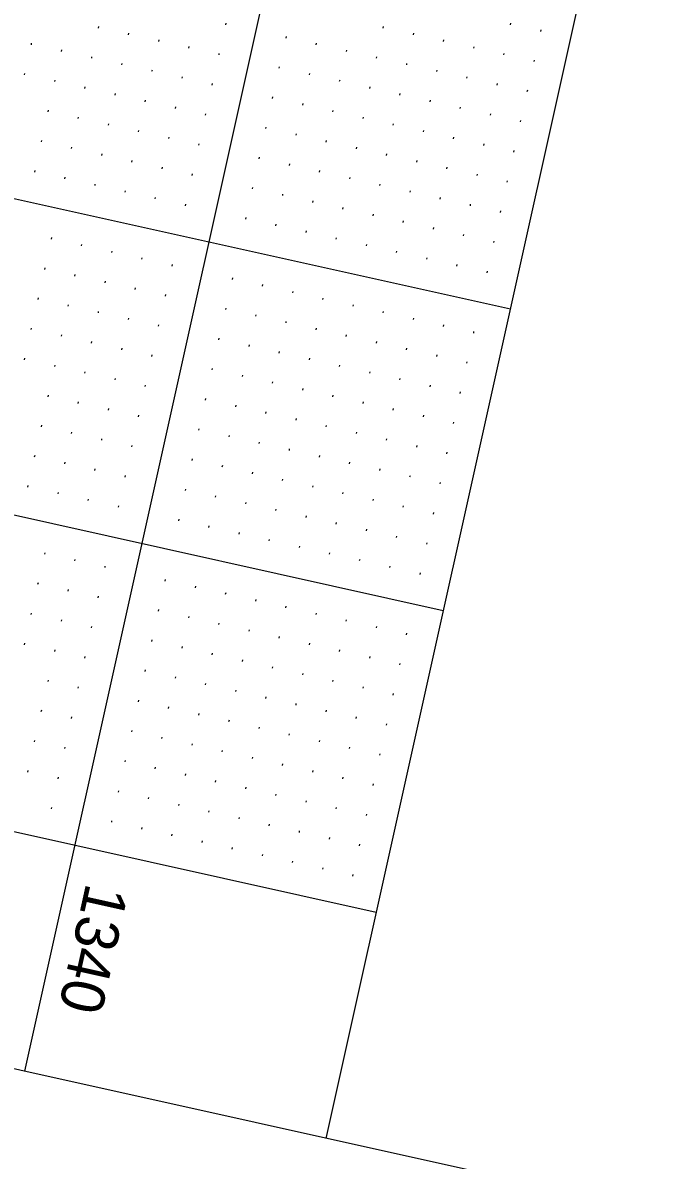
# Model space of a CAD drawing. Extents: x 2149268 to 2150830, y 142155 to 144285.
# Drawn here: x 2149815.9 to 2149919.9, y 142325.7 to 142509.8 of the extents above; entities that cross this region are included whole.
import ezdxf

# ---------------------------------------------------------------- set-up
doc = ezdxf.new("R2010")
doc.units = 0
for name, color, linetype in [('SHT_Plan_Profile_Sheet_Elev_Txt', 7, 'Continuous'), ('SHT_Profile_Grid_Major', 7, 'Continuous'), ('SHT_Profile_Grid_Minor', 7, 'Continuous'), ('SHT_Sheet_Border', 7, 'Continuous')]:
    doc.layers.add(name, color=color, linetype=linetype)

msp = doc.modelspace()

# ---------------------------------------------------------------- linework, layer by layer
at = {"layer": 'SHT_Profile_Grid_Major'}
for p, q in [((2150158.06, 143877.55), (2149816.2, 142340.1)), ((2149504.39, 142550.29), (2149894.85, 142463.47)), ((2149493.54, 142501.48), (2149884, 142414.66))]:
    msp.add_line(p, q, dxfattribs=at)
at = {"layer": 'SHT_Profile_Grid_Minor'}
for p, q in [((2149828.18, 142509.15), (2149828.12, 142508.91)), ((2149833.06, 142508.07), (2149833.01, 142507.82)), ((2149848.79, 142509.69), (2149848.73, 142509.45)), ((2149874.28, 142509.15), (2149874.22, 142508.9)), ((2149879.16, 142508.06), (2149879.1, 142507.82)), ((2149894.88, 142509.69), (2149894.83, 142509.44)), ((2149899.77, 142508.6), (2149899.71, 142508.36)), ((2149817.33, 142506.44), (2149817.28, 142506.2)), ((2149837.94, 142506.98), (2149837.89, 142506.74)), ((2149858.55, 142507.52), (2149858.49, 142507.28)), ((2149863.43, 142506.44), (2149863.38, 142506.19)), ((2149884.04, 142506.98), (2149883.98, 142506.73)), ((2149822.21, 142505.36), (2149822.16, 142505.11)), ((2149827.09, 142504.27), (2149827.04, 142504.03)), ((2149842.82, 142505.9), (2149842.77, 142505.65)), ((2149847.7, 142504.81), (2149847.65, 142504.57)), ((2149868.31, 142505.35), (2149868.26, 142505.11)), ((2149873.19, 142504.27), (2149873.14, 142504.02)), ((2149888.92, 142505.89), (2149888.86, 142505.65)), ((2149893.8, 142504.81), (2149893.75, 142504.56)), ((2149831.97, 142503.19), (2149831.92, 142502.94)), ((2149857.46, 142502.64), (2149857.41, 142502.4)), ((2149878.07, 142503.18), (2149878.02, 142502.94)), ((2149898.68, 142503.72), (2149898.63, 142503.48)), ((2149816.25, 142501.56), (2149816.19, 142501.32)), ((2149836.86, 142502.1), (2149836.8, 142501.86)), ((2149841.74, 142501.02), (2149841.68, 142500.77)), ((2149862.34, 142501.56), (2149862.29, 142501.31)), ((2149882.95, 142502.1), (2149882.9, 142501.85)), ((2149887.83, 142501.01), (2149887.78, 142500.77)), ((2149821.13, 142500.48), (2149821.07, 142500.23)), ((2149826.01, 142499.39), (2149825.95, 142499.15)), ((2149846.62, 142499.93), (2149846.56, 142499.69)), ((2149867.23, 142500.47), (2149867.17, 142500.23)), ((2149872.11, 142499.39), (2149872.05, 142499.14)), ((2149892.71, 142499.92), (2149892.66, 142499.68)), ((2149897.6, 142498.84), (2149897.54, 142498.6)), ((2149830.89, 142498.31), (2149830.83, 142498.06)), ((2149835.77, 142497.22), (2149835.72, 142496.98)), ((2149856.38, 142497.76), (2149856.32, 142497.52)), ((2149876.99, 142498.3), (2149876.93, 142498.06)), ((2149881.87, 142497.21), (2149881.81, 142496.97)), ((2149820.04, 142495.6), (2149819.99, 142495.35)), ((2149840.65, 142496.14), (2149840.6, 142495.89)), ((2149845.53, 142495.05), (2149845.48, 142494.81)), ((2149861.26, 142496.67), (2149861.2, 142496.43)), ((2149866.14, 142495.59), (2149866.09, 142495.35)), ((2149886.75, 142496.13), (2149886.69, 142495.89)), ((2149891.63, 142495.04), (2149891.57, 142494.8)), ((2149824.92, 142494.51), (2149824.87, 142494.27)), ((2149829.8, 142493.43), (2149829.75, 142493.18)), ((2149871.02, 142494.5), (2149870.97, 142494.26)), ((2149875.9, 142493.42), (2149875.85, 142493.18)), ((2149896.51, 142493.96), (2149896.46, 142493.71)), ((2149834.68, 142492.34), (2149834.63, 142492.1)), ((2149855.29, 142492.88), (2149855.24, 142492.64)), ((2149860.17, 142491.79), (2149860.12, 142491.55)), ((2149880.78, 142492.33), (2149880.73, 142492.09)), ((2149818.96, 142490.71), (2149818.9, 142490.47)), ((2149823.84, 142489.63), (2149823.78, 142489.39)), ((2149839.57, 142491.25), (2149839.51, 142491.01)), ((2149844.45, 142490.17), (2149844.39, 142489.93)), ((2149865.05, 142490.71), (2149865, 142490.46)), ((2149869.94, 142489.62), (2149869.88, 142489.38)), ((2149885.66, 142491.25), (2149885.61, 142491)), ((2149890.54, 142490.16), (2149890.49, 142489.92)), ((2149828.72, 142488.54), (2149828.66, 142488.3)), ((2149854.21, 142488), (2149854.15, 142487.75)), ((2149874.82, 142488.54), (2149874.76, 142488.29)), ((2149895.42, 142489.08), (2149895.37, 142488.83)), ((2149833.6, 142487.46), (2149833.55, 142487.22)), ((2149838.48, 142486.37), (2149838.43, 142486.13)), ((2149859.09, 142486.91), (2149859.03, 142486.67)), ((2149879.7, 142487.45), (2149879.64, 142487.21)), ((2149884.58, 142486.37), (2149884.52, 142486.12)), ((2149817.87, 142485.83), (2149817.82, 142485.59)), ((2149822.75, 142484.75), (2149822.7, 142484.5)), ((2149843.36, 142485.29), (2149843.31, 142485.04)), ((2149863.97, 142485.83), (2149863.92, 142485.58)), ((2149868.85, 142484.74), (2149868.8, 142484.5)), ((2149889.46, 142485.28), (2149889.4, 142485.04)), ((2149894.34, 142484.2), (2149894.29, 142483.95)), ((2149827.63, 142483.66), (2149827.58, 142483.42)), ((2149832.51, 142482.58), (2149832.46, 142482.33)), ((2149853.12, 142483.12), (2149853.07, 142482.87)), ((2149873.73, 142483.66), (2149873.68, 142483.41)), ((2149878.61, 142482.57), (2149878.56, 142482.33)), ((2149837.39, 142481.49), (2149837.34, 142481.25)), ((2149842.28, 142480.41), (2149842.22, 142480.16)), ((2149858, 142482.03), (2149857.95, 142481.79)), ((2149862.88, 142480.95), (2149862.83, 142480.7)), ((2149883.49, 142481.49), (2149883.44, 142481.24)), ((2149888.37, 142480.4), (2149888.32, 142480.16)), ((2149867.76, 142479.86), (2149867.71, 142479.62)), ((2149872.65, 142478.78), (2149872.59, 142478.53)), ((2149893.25, 142479.32), (2149893.2, 142479.07)), ((2149852.04, 142478.24), (2149851.98, 142477.99)), ((2149856.92, 142477.15), (2149856.86, 142476.91)), ((2149877.53, 142477.69), (2149877.47, 142477.45)), ((2149820.58, 142474.99), (2149820.53, 142474.74)), ((2149861.8, 142476.07), (2149861.74, 142475.82)), ((2149866.68, 142474.98), (2149866.63, 142474.74)), ((2149882.41, 142476.61), (2149882.35, 142476.36)), ((2149887.29, 142475.52), (2149887.23, 142475.28)), ((2149825.46, 142473.9), (2149825.41, 142473.66)), ((2149871.56, 142473.9), (2149871.51, 142473.65)), ((2149892.17, 142474.44), (2149892.11, 142474.19)), ((2149830.34, 142472.82), (2149830.29, 142472.57)), ((2149835.22, 142471.73), (2149835.17, 142471.49)), ((2149876.44, 142472.81), (2149876.39, 142472.57)), ((2149881.32, 142471.73), (2149881.27, 142471.48)), ((2149819.5, 142470.11), (2149819.44, 142469.86)), ((2149840.1, 142470.65), (2149840.05, 142470.4)), ((2149886.2, 142470.64), (2149886.15, 142470.4)), ((2149891.08, 142469.55), (2149891.03, 142469.31)), ((2149824.38, 142469.02), (2149824.32, 142468.78)), ((2149829.26, 142467.94), (2149829.2, 142467.69)), ((2149849.87, 142468.48), (2149849.81, 142468.23)), ((2149834.14, 142466.85), (2149834.08, 142466.61)), ((2149839.02, 142465.77), (2149838.97, 142465.52)), ((2149854.75, 142467.39), (2149854.69, 142467.15)), ((2149859.63, 142466.3), (2149859.57, 142466.06)), ((2149818.41, 142465.23), (2149818.36, 142464.98)), ((2149823.29, 142464.14), (2149823.24, 142463.9)), ((2149864.51, 142465.22), (2149864.45, 142464.98)), ((2149869.39, 142464.13), (2149869.34, 142463.89)), ((2149828.17, 142463.06), (2149828.12, 142462.81)), ((2149833.05, 142461.97), (2149833, 142461.73)), ((2149848.78, 142463.59), (2149848.73, 142463.35)), ((2149853.66, 142462.51), (2149853.61, 142462.27)), ((2149874.27, 142463.05), (2149874.22, 142462.81)), ((2149879.15, 142461.96), (2149879.1, 142461.72)), ((2149817.33, 142460.34), (2149817.27, 142460.1)), ((2149837.93, 142460.88), (2149837.88, 142460.64)), ((2149858.54, 142461.42), (2149858.49, 142461.18)), ((2149863.42, 142460.34), (2149863.37, 142460.09)), ((2149884.03, 142460.88), (2149883.98, 142460.63)), ((2149822.21, 142459.26), (2149822.15, 142459.02)), ((2149847.7, 142458.71), (2149847.64, 142458.47)), ((2149868.3, 142459.25), (2149868.25, 142459.01)), ((2149888.91, 142459.79), (2149888.86, 142459.55)), ((2149827.09, 142458.17), (2149827.03, 142457.93)), ((2149831.97, 142457.09), (2149831.91, 142456.84)), ((2149852.58, 142457.63), (2149852.52, 142457.38)), ((2149857.46, 142456.54), (2149857.4, 142456.3)), ((2149873.19, 142458.17), (2149873.13, 142457.92)), ((2149878.07, 142457.08), (2149878.01, 142456.84)), ((2149816.24, 142455.46), (2149816.19, 142455.22)), ((2149836.85, 142456), (2149836.79, 142455.76)), ((2149862.34, 142455.46), (2149862.28, 142455.21)), ((2149882.95, 142456), (2149882.89, 142455.75)), ((2149887.83, 142454.91), (2149887.77, 142454.67)), ((2149821.12, 142454.38), (2149821.07, 142454.13)), ((2149826, 142453.29), (2149825.95, 142453.05)), ((2149846.61, 142453.83), (2149846.56, 142453.59)), ((2149851.49, 142452.75), (2149851.44, 142452.5)), ((2149867.22, 142454.37), (2149867.16, 142454.13)), ((2149872.1, 142453.29), (2149872.05, 142453.04)), ((2149830.88, 142452.21), (2149830.83, 142451.96)), ((2149835.76, 142451.12), (2149835.71, 142450.88)), ((2149856.37, 142451.66), (2149856.32, 142451.42)), ((2149876.98, 142452.2), (2149876.93, 142451.96)), ((2149881.86, 142451.12), (2149881.81, 142450.87)), ((2149820.04, 142449.5), (2149819.98, 142449.25)), ((2149861.25, 142450.58), (2149861.2, 142450.33)), ((2149866.13, 142449.49), (2149866.08, 142449.25)), ((2149886.74, 142450.03), (2149886.69, 142449.79)), ((2149824.92, 142448.41), (2149824.86, 142448.17)), ((2149829.8, 142447.33), (2149829.74, 142447.08)), ((2149845.53, 142448.95), (2149845.47, 142448.71)), ((2149850.41, 142447.87), (2149850.35, 142447.62)), ((2149871.01, 142448.41), (2149870.96, 142448.16)), ((2149875.9, 142447.32), (2149875.84, 142447.08)), ((2149834.68, 142446.24), (2149834.62, 142446)), ((2149855.29, 142446.78), (2149855.23, 142446.54)), ((2149860.17, 142445.7), (2149860.11, 142445.45)), ((2149880.78, 142446.24), (2149880.72, 142445.99)), ((2149818.95, 142444.62), (2149818.9, 142444.37)), ((2149823.83, 142443.53), (2149823.78, 142443.29)), ((2149844.44, 142444.07), (2149844.39, 142443.83)), ((2149865.05, 142444.61), (2149864.99, 142444.37)), ((2149869.93, 142443.53), (2149869.88, 142443.28)), ((2149885.66, 142445.15), (2149885.6, 142444.91)), ((2149828.71, 142442.45), (2149828.66, 142442.2)), ((2149849.32, 142442.99), (2149849.27, 142442.74)), ((2149854.2, 142441.9), (2149854.15, 142441.66)), ((2149874.81, 142442.44), (2149874.76, 142442.2)), ((2149833.59, 142441.36), (2149833.54, 142441.12)), ((2149859.08, 142440.82), (2149859.03, 142440.57)), ((2149879.69, 142441.36), (2149879.64, 142441.11)), ((2149884.57, 142440.27), (2149884.52, 142440.03)), ((2149817.87, 142439.74), (2149817.81, 142439.49)), ((2149822.75, 142438.65), (2149822.69, 142438.41)), ((2149843.35, 142439.19), (2149843.3, 142438.95)), ((2149848.24, 142438.11), (2149848.18, 142437.86)), ((2149863.96, 142439.73), (2149863.91, 142439.49)), ((2149868.84, 142438.65), (2149868.79, 142438.4)), ((2149827.63, 142437.57), (2149827.57, 142437.32)), ((2149832.51, 142436.48), (2149832.45, 142436.24)), ((2149853.12, 142437.02), (2149853.06, 142436.78)), ((2149873.72, 142437.56), (2149873.67, 142437.32)), ((2149878.61, 142436.47), (2149878.55, 142436.23)), ((2149816.78, 142434.86), (2149816.73, 142434.61)), ((2149842.27, 142434.31), (2149842.22, 142434.07)), ((2149858, 142435.93), (2149857.94, 142435.69)), ((2149862.88, 142434.85), (2149862.82, 142434.61)), ((2149883.49, 142435.39), (2149883.43, 142435.15)), ((2149821.66, 142433.77), (2149821.61, 142433.53)), ((2149826.54, 142432.69), (2149826.49, 142432.44)), ((2149847.15, 142433.22), (2149847.1, 142432.98)), ((2149867.76, 142433.76), (2149867.7, 142433.52)), ((2149872.64, 142432.68), (2149872.59, 142432.44)), ((2149831.42, 142431.6), (2149831.37, 142431.36)), ((2149852.03, 142432.14), (2149851.98, 142431.9)), ((2149856.91, 142431.05), (2149856.86, 142430.81)), ((2149877.52, 142431.59), (2149877.47, 142431.35)), ((2149841.18, 142429.43), (2149841.13, 142429.19)), ((2149861.79, 142429.97), (2149861.74, 142429.72)), ((2149866.67, 142428.88), (2149866.62, 142428.64)), ((2149882.4, 142430.51), (2149882.35, 142430.26)), ((2149846.07, 142428.34), (2149846.01, 142428.1)), ((2149850.95, 142427.26), (2149850.89, 142427.01)), ((2149871.55, 142427.8), (2149871.5, 142427.55)), ((2149855.83, 142426.17), (2149855.77, 142425.93)), ((2149876.44, 142426.71), (2149876.38, 142426.47)), ((2149881.32, 142425.63), (2149881.26, 142425.38)), ((2149819.49, 142424.01), (2149819.44, 142423.76)), ((2149860.71, 142425.09), (2149860.65, 142424.84)), ((2149865.59, 142424), (2149865.53, 142423.76)), ((2149824.37, 142422.92), (2149824.32, 142422.68)), ((2149829.25, 142421.84), (2149829.2, 142421.59)), ((2149870.47, 142422.92), (2149870.41, 142422.67)), ((2149875.35, 142421.83), (2149875.3, 142421.59)), ((2149839.01, 142419.67), (2149838.96, 142419.42)), ((2149880.23, 142420.75), (2149880.18, 142420.5)), ((2149818.41, 142419.13), (2149818.35, 142418.88)), ((2149823.29, 142418.04), (2149823.23, 142417.8)), ((2149843.89, 142418.58), (2149843.84, 142418.34)), ((2149828.17, 142416.96), (2149828.11, 142416.71)), ((2149848.78, 142417.5), (2149848.72, 142417.25)), ((2149853.66, 142416.41), (2149853.6, 142416.17)), ((2149817.32, 142414.25), (2149817.27, 142414)), ((2149837.93, 142414.79), (2149837.87, 142414.54)), ((2149858.54, 142415.33), (2149858.48, 142415.08)), ((2149863.42, 142414.24), (2149863.36, 142414)), ((2149822.2, 142413.16), (2149822.15, 142412.92)), ((2149842.81, 142413.7), (2149842.76, 142413.46)), ((2149847.69, 142412.62), (2149847.64, 142412.37)), ((2149868.3, 142413.16), (2149868.24, 142412.91)), ((2149827.08, 142412.08), (2149827.03, 142411.83)), ((2149852.57, 142411.53), (2149852.52, 142411.29)), ((2149857.45, 142410.45), (2149857.4, 142410.2)), ((2149873.18, 142412.07), (2149873.13, 142411.83)), ((2149878.06, 142410.99), (2149878.01, 142410.74)), ((2149816.23, 142409.37), (2149816.18, 142409.12)), ((2149836.84, 142409.91), (2149836.79, 142409.66)), ((2149841.72, 142408.82), (2149841.67, 142408.58)), ((2149862.33, 142409.36), (2149862.28, 142409.12)), ((2149821.12, 142408.28), (2149821.06, 142408.04)), ((2149826, 142407.2), (2149825.94, 142406.95)), ((2149846.6, 142407.74), (2149846.55, 142407.49)), ((2149867.21, 142408.28), (2149867.16, 142408.03)), ((2149872.09, 142407.19), (2149872.04, 142406.95)), ((2149835.76, 142405.03), (2149835.7, 142404.78)), ((2149851.49, 142406.65), (2149851.43, 142406.41)), ((2149856.37, 142405.56), (2149856.31, 142405.32)), ((2149876.97, 142406.1), (2149876.92, 142405.86)), ((2149820.03, 142403.4), (2149819.98, 142403.16)), ((2149840.64, 142403.94), (2149840.58, 142403.7)), ((2149861.25, 142404.48), (2149861.19, 142404.24)), ((2149866.13, 142403.39), (2149866.07, 142403.15)), ((2149824.91, 142402.31), (2149824.86, 142402.07)), ((2149845.52, 142402.85), (2149845.47, 142402.61)), ((2149850.4, 142401.77), (2149850.35, 142401.53)), ((2149871.01, 142402.31), (2149870.95, 142402.06)), ((2149875.89, 142401.22), (2149875.84, 142400.98)), ((2149834.67, 142400.14), (2149834.62, 142399.9)), ((2149855.28, 142400.68), (2149855.23, 142400.44)), ((2149860.16, 142399.6), (2149860.11, 142399.35)), ((2149818.95, 142398.52), (2149818.89, 142398.28)), ((2149839.55, 142399.06), (2149839.5, 142398.82)), ((2149844.43, 142397.97), (2149844.38, 142397.73)), ((2149865.04, 142398.51), (2149864.99, 142398.27)), ((2149823.83, 142397.43), (2149823.77, 142397.19)), ((2149849.32, 142396.89), (2149849.26, 142396.64)), ((2149854.2, 142395.8), (2149854.14, 142395.56)), ((2149869.92, 142397.43), (2149869.87, 142397.18)), ((2149874.8, 142396.34), (2149874.75, 142396.1)), ((2149833.59, 142395.26), (2149833.53, 142395.02)), ((2149838.47, 142394.18), (2149838.41, 142393.93)), ((2149859.08, 142394.72), (2149859.02, 142394.47)), ((2149817.86, 142393.64), (2149817.81, 142393.39)), ((2149822.74, 142392.55), (2149822.69, 142392.31)), ((2149843.35, 142393.09), (2149843.29, 142392.85)), ((2149848.23, 142392.01), (2149848.18, 142391.76)), ((2149863.96, 142393.63), (2149863.9, 142393.39)), ((2149868.84, 142392.55), (2149868.78, 142392.3)), ((2149832.5, 142390.38), (2149832.45, 142390.14)), ((2149853.11, 142390.92), (2149853.06, 142390.68)), ((2149873.72, 142391.46), (2149873.66, 142391.22)), ((2149816.77, 142388.76), (2149816.72, 142388.51)), ((2149837.38, 142389.3), (2149837.33, 142389.05)), ((2149857.99, 142389.84), (2149857.94, 142389.59)), ((2149862.87, 142388.75), (2149862.82, 142388.51)), ((2149821.66, 142387.67), (2149821.6, 142387.43)), ((2149842.26, 142388.21), (2149842.21, 142387.97)), ((2149847.14, 142387.13), (2149847.09, 142386.88)), ((2149867.75, 142387.67), (2149867.7, 142387.42)), ((2149872.63, 142386.58), (2149872.58, 142386.34)), ((2149831.42, 142385.5), (2149831.36, 142385.26)), ((2149852.03, 142386.04), (2149851.97, 142385.8)), ((2149856.91, 142384.96), (2149856.85, 142384.71)), ((2149820.57, 142382.79), (2149820.52, 142382.55)), ((2149836.3, 142384.42), (2149836.24, 142384.17)), ((2149841.18, 142383.33), (2149841.12, 142383.09)), ((2149861.79, 142383.87), (2149861.73, 142383.63)), ((2149866.67, 142382.79), (2149866.61, 142382.54)), ((2149846.06, 142382.25), (2149846.01, 142382)), ((2149850.94, 142381.16), (2149850.89, 142380.92)), ((2149871.55, 142381.7), (2149871.49, 142381.46)), ((2149830.33, 142380.62), (2149830.28, 142380.38)), ((2149835.21, 142379.54), (2149835.16, 142379.29)), ((2149855.82, 142380.08), (2149855.77, 142379.83)), ((2149840.09, 142378.45), (2149840.04, 142378.21)), ((2149844.97, 142377.37), (2149844.92, 142377.12)), ((2149860.7, 142378.99), (2149860.65, 142378.75)), ((2149865.58, 142377.91), (2149865.53, 142377.66)), ((2149849.85, 142376.28), (2149849.8, 142376.04)), ((2149870.46, 142376.82), (2149870.41, 142376.58)), ((2149854.74, 142375.19), (2149854.68, 142374.95)), ((2149859.62, 142374.11), (2149859.56, 142373.87)), ((2149864.5, 142373.02), (2149864.44, 142372.78)), ((2149869.38, 142371.94), (2149869.32, 142371.69))]:
    msp.add_line(p, q, dxfattribs=at)
at = {"layer": 'SHT_Sheet_Border'}
for p, q in [((2150206.87, 143866.7), (2149865.01, 142329.24)), ((2149409.47, 142468.95), (2149873.15, 142365.85))]:
    msp.add_line(p, q, dxfattribs=at)
msp.add_lwpolyline([(2150726.67, 143751.11), (2150384.81, 142213.66), (2149359.84, 142441.57), (2149701.71, 143979.02)], close=True, dxfattribs=at)

# ---------------------------------------------------------------- texts
at = {"layer": 'SHT_Plan_Profile_Sheet_Elev_Txt'}
msp.add_text('1340', height=7, rotation=257.4638, dxfattribs=at).set_placement((2149826.25, 142370.75))

doc.saveas('drawing.dxf')
